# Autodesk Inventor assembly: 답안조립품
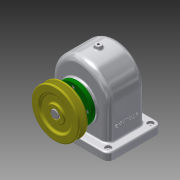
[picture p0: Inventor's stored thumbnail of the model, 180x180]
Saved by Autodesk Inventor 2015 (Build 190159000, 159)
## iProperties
Created: 2016-10
Part Number: 답안조립품
Document SubType Name: Assembly
Designer: LineLG02
Author: LineLG02
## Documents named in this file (15)
- C:\Users\LineLG02\Desktop\461007V1006\답안조립품.iam
- C:\Users\LineLG02\Desktop\461007V1006\본체.ipt
- C:\Users\LineLG02\Desktop\461007V1006\베어링 6203.ipt
- C:\Users\LineLG02\Desktop\461007V1006\뒤커버.ipt
- C:\Users\LineLG02\Desktop\461007V1006\앞커버.ipt
- C:\Users\LineLG02\Desktop\461007V1006\축.ipt
- C:\Users\LineLG02\Desktop\461007V1006\키 - 6 x 6 x 22.ipt
- C:\Users\LineLG02\Desktop\461007V1006\키 - 5 x 5 x 18.ipt
- C:\Users\LineLG02\Desktop\461007V1006\부시.ipt
- C:\Users\LineLG02\Desktop\461007V1006\오일씰 28 40 8.ipt
- C:\Users\LineLG02\Desktop\461007V1006\스퍼기어.ipt
- C:\Users\LineLG02\Desktop\461007V1006\볼트 M3 x 10.ipt
- C:\Users\LineLG02\Desktop\461007V1006\볼트 M3 x 8.ipt
- C:\Users\LineLG02\Desktop\461007V1006\V-벨트풀리.ipt
- C:\Users\LineLG02\Desktop\461007V1006\멈춤나사 - M4x10.ipt
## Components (9 placed, 3 different names)
1. V-벨트풀리:1 — 각도:4, 각도:5
2. ISO 4762 M3 x 10:1 — 각도:2
3. ISO 4762 M3 x 10:2
4. ISO 4762 M3 x 10:3
5. ISO 4762 M3 x 10:4
6. ISO 4762 M3 x 8:1 — 각도:3
7. ISO 4762 M3 x 8:2
8. ISO 4762 M3 x 8:3
9. ISO 4762 M3 x 8:4
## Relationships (4: Angle 4)
- 각도:2 [Angle]: ISO 4762 M3 x 10:1
- 각도:3 [Angle]: ISO 4762 M3 x 8:1
- 각도:4 [Angle]: V-벨트풀리:1
- 각도:5 [Angle]: V-벨트풀리:1
